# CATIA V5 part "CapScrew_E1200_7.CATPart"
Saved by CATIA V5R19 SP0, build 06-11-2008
Part number: CapScrew_E1200_7
Nomenclature: E 1200/6x30
Source: Unknown
Description: MEUSBURGER
Bounding box of the stored display mesh (mm): x -4.991 to 4.998, y -5 to 5, z 0 to 36
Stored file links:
  C:\Users\jsmid\Desktop\DP_Smidak_Forma LEGO\CapScrew_E1200_7.CATPart
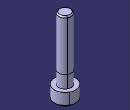
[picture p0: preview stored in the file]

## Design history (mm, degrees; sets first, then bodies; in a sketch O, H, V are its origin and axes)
Body1 (main body)
  Solid1 "PartBody": solid without history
